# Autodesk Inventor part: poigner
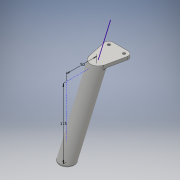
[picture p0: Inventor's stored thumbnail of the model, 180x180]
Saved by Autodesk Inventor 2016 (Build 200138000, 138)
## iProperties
Created: 2016-01
Part Number: poigner
Material: Generic
Document SubType Name: Modeling
Designer: Peter
Density: 1 g/cm^3
Appearance: Default
Author: Peter
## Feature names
1. Balayage1
2. Extrusion1
3. Balayage2
4. Congé3 [Fillet]
5. Congé4 [Fillet]
## Parameters: d0 = 25 mm, d1 = 115 mm, d3 = 0, d4 = 0, d6 = 4 mm, d8 = 5 mm, d9 = 25 mm, d10 = 5 mm, d11 = 0, d13 = 0, d14 = 0, d15 = 2 mm, d16 = 2 mm
